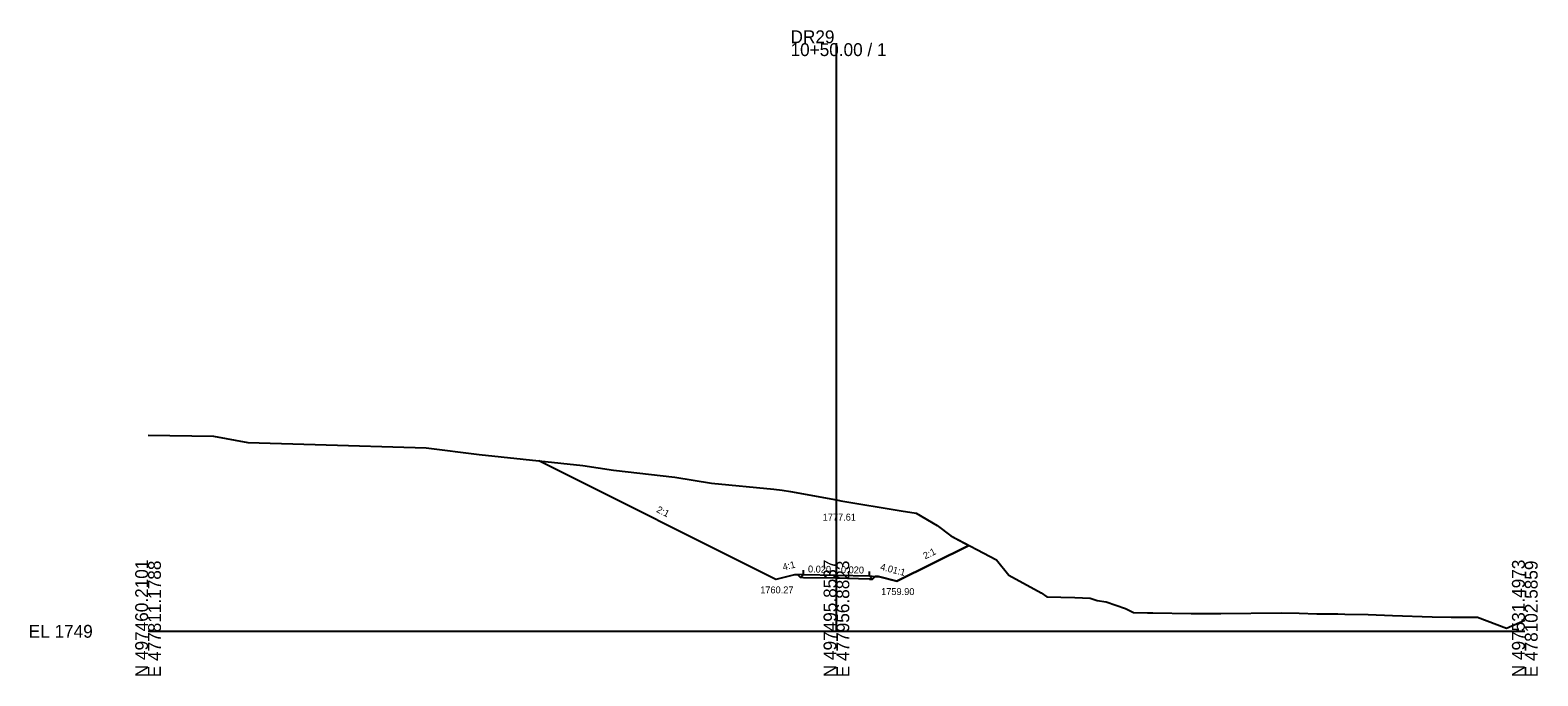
# Model space of a CAD drawing. Extents: x -26 to 303, y -10 to 4734.
# Drawn here: x -25.7 to 302.8, y 990.3 to 1130.9 of the extents above; entities that cross this region are included whole.
import ezdxf

# ---------------------------------------------------------------- set-up
doc = ezdxf.new("R2010")
doc.units = 0
for name, color, linetype in [('Exist Cross Section Cell', 7, 'Continuous'), ('Exist XS Center Line Elevation Label', 7, 'Continuous'), ('Exist XS Ground Line', 7, 'Continuous'), ('Prop XS Ditch Slope Text', 7, 'Continuous'), ('Prop XS Ditch Standard Text', 7, 'Continuous'), ('Prop XS Dump Level', 7, 'Continuous'), ('Prop XS Earthwork Shape', 7, 'Continuous'), ('Prop XS EOT Tick Mark', 7, 'Continuous'), ('Prop XS Finish Grade', 7, 'Continuous'), ('Prop XS Finish Grade Earthwork', 7, 'Continuous'), ('Prop XS Finish Grade Pavement', 7, 'Continuous'), ('Prop XS Pvmt Edge Slope', 7, 'Continuous'), ('Prop XS SE Text', 7, 'Continuous'), ('Prop XS Shoulder Borrow Shape', 7, 'Continuous'), ('Prop XS Side Slope Text', 7, 'Continuous'), ('Prop XS Subgrade Earthwork', 7, 'Continuous')]:
    doc.layers.add(name, color=color, linetype=linetype)

msp = doc.modelspace()

# ---------------------------------------------------------------- linework, layer by layer
at = {"layer": 'Exist Cross Section Cell'}
for p, q in [((150, 1000), (150, 1128.06)), ((0, 1000), (150, 1000)), ((150, 1000), (300, 1000))]:
    msp.add_line(p, q, dxfattribs=at)
at = {"layer": 'Exist XS Ground Line'}
msp.add_lwpolyline([(0, 1042.69), (14.27, 1042.47), (21.75, 1041.13), (36.4, 1040.66), (60.61, 1039.92), (72.14, 1038.47), (94.73, 1036.07), (101.42, 1035.12), (114.79, 1033.59), (122.81, 1032.28), (136.35, 1030.96), (138.15, 1030.74), (139.96, 1030.46), (150, 1028.61), (150.97, 1028.43), (164.13, 1026.23), (167.36, 1025.7), (171.98, 1023.04), (174.95, 1020.78), (184.9, 1015.53), (187.59, 1012.22), (194.64, 1008.37), (195.84, 1007.5), (201.96, 1007.34), (205.26, 1007.19), (206.79, 1006.69), (208.79, 1006.41), (213.01, 1004.95), (214.73, 1004.09), (217.76, 1004.01), (218.96, 1004), (227.3, 1003.9), (228.5, 1003.89), (233.79, 1003.86), (246.89, 1004.01), (250.83, 1003.95), (254.7, 1003.83), (255.27, 1003.83), (259.27, 1003.77), (260.75, 1003.76), (265.83, 1003.68), (271.17, 1003.47), (279.81, 1003.16), (283.97, 1003.1), (289.7, 1003.06), (293.89, 1001.5), (296.01, 1000.71), (300, 1002.41)], dxfattribs=at)
at = {"layer": 'Prop XS Dump Level'}
for p, q in [((142.83, 1012.35), (150, 1012.2)), ((150, 1012.2), (157.18, 1012.06))]:
    msp.add_line(p, q, dxfattribs=at)
at = {"layer": 'Prop XS Earthwork Shape'}
for points in [[(136.82, 1011.27), (85.14, 1037.09), (94.73, 1036.07), (101.42, 1035.12), (114.79, 1033.59), (122.81, 1032.28), (136.35, 1030.96), (138.15, 1030.74), (139.96, 1030.46), (150, 1028.61), (150.97, 1028.43), (164.13, 1026.23), (167.36, 1025.7), (171.98, 1023.04), (174.95, 1020.78), (178.86, 1018.72), (163.19, 1010.9), (159.19, 1011.9), (158.44, 1011.96), (157.86, 1011.38), (157.18, 1011.39), (150, 1011.54), (142.83, 1011.68), (142.17, 1011.69), (141.57, 1012.3), (140.83, 1012.27)], [(157.18, 1011.39), (150, 1011.54), (142.83, 1011.68), (142.17, 1011.69), (141.57, 1012.3), (140.83, 1012.27), (136.82, 1011.27), (85.14, 1037.09), (94.73, 1036.07), (101.42, 1035.12), (114.79, 1033.59), (122.81, 1032.28), (136.35, 1030.96), (138.15, 1030.74), (139.96, 1030.46), (150, 1028.61), (150.97, 1028.43), (164.13, 1026.23), (167.36, 1025.7), (171.98, 1023.04), (174.95, 1020.78), (178.86, 1018.72), (163.19, 1010.9), (159.19, 1011.9), (158.44, 1011.96), (157.86, 1011.38)]]:
    msp.add_lwpolyline(points, close=True, dxfattribs=at)
at = {"layer": 'Prop XS EOT Tick Mark'}
for p, q in [((142.83, 1012.35), (142.83, 1013.35)), ((157.18, 1012.06), (157.18, 1013.06))]:
    msp.add_line(p, q, dxfattribs=at)
at = {"layer": 'Prop XS Finish Grade'}
for p, q in [((142.83, 1012.35), (141.57, 1012.3)), ((157.18, 1012.06), (158.44, 1011.96))]:
    msp.add_line(p, q, dxfattribs=at)
at = {"layer": 'Prop XS Finish Grade Earthwork'}
for p, q in [((136.82, 1011.27), (85.14, 1037.09)), ((163.19, 1010.9), (178.86, 1018.72)), ((140.83, 1012.27), (136.82, 1011.27)), ((141.57, 1012.3), (140.83, 1012.27)), ((158.44, 1011.96), (159.19, 1011.9)), ((159.19, 1011.9), (163.19, 1010.9))]:
    msp.add_line(p, q, dxfattribs=at)
at = {"layer": 'Prop XS Finish Grade Pavement'}
for p, q in [((142.83, 1012.35), (150, 1012.2)), ((150, 1012.2), (157.18, 1012.06))]:
    msp.add_line(p, q, dxfattribs=at)
at = {"layer": 'Prop XS Pvmt Edge Slope'}
for p, q in [((142.83, 1012.35), (142.17, 1011.69)), ((157.18, 1012.06), (157.86, 1011.38))]:
    msp.add_line(p, q, dxfattribs=at)
at = {"layer": 'Prop XS Shoulder Borrow Shape'}
for points in [[(142.83, 1012.35), (141.57, 1012.3), (142.17, 1011.69)], [(157.18, 1012.06), (158.44, 1011.96), (157.86, 1011.38)]]:
    msp.add_lwpolyline(points, close=True, dxfattribs=at)
at = {"layer": 'Prop XS Subgrade Earthwork'}
for p, q in [((142.17, 1011.69), (141.57, 1012.3)), ((157.86, 1011.38), (158.44, 1011.96)), ((142.83, 1011.68), (142.17, 1011.69)), ((150, 1011.54), (142.83, 1011.68)), ((157.18, 1011.39), (150, 1011.54)), ((157.18, 1011.39), (157.86, 1011.38))]:
    msp.add_line(p, q, dxfattribs=at)

# ---------------------------------------------------------------- texts
at = {"layer": 'Exist Cross Section Cell'}
for s, p in [('DR29', (140, 1128.06)), ('10+50.00 / 1', (140, 1125.26)), ('EL 1749', (-26, 998.6))]:
    msp.add_text(s, height=2.8, dxfattribs=at).set_placement(p)
for s, p in [('N 497460.2101', (0, 990)), ('E 477811.1788', (2.8, 990)), ('N 497495.8537', (150, 990)), ('E 477956.8823', (152.8, 990)), ('N 497531.4973', (300, 990)), ('E 478102.5859', (302.8, 990))]:
    msp.add_text(s, height=2.8, rotation=90, dxfattribs=at).set_placement(p)
at = {"layer": 'Exist XS Center Line Elevation Label'}
msp.add_text('1777.61', height=1.5, dxfattribs=at).set_placement((147, 1024.11))
at = {"layer": 'Prop XS Ditch Slope Text'}
for s, rotation, p in [('4:1', 14.0283, (138.46, 1013.22)), ('4.01:1', 345.9841, (159.43, 1013.38))]:
    msp.add_text(s, height=1.5, rotation=rotation, dxfattribs=at).set_placement(p)
at = {"layer": 'Prop XS Ditch Standard Text'}
for s, p in [('1760.27', (133.39, 1008.27)), ('1759.90', (159.74, 1007.9))]:
    msp.add_text(s, height=1.5, dxfattribs=at).set_placement(p)
at = {"layer": 'Prop XS Dump Level'}
for p in [(140.83, 1012.23), (159.19, 1011.86)]:
    msp.add_text('Case1', height=0.04, dxfattribs=at).set_placement(p)
at = {"layer": 'Prop XS SE Text'}
for p in [(143.79, 1012.83), (150.97, 1012.68)]:
    msp.add_text('0.020', height=1.5, rotation=358.8542, dxfattribs=at).set_placement(p)
at = {"layer": 'Prop XS Side Slope Text'}
for rotation, p in [(333.4485, (110.64, 1026.03)), (26.5305, (169.34, 1015.64))]:
    msp.add_text('2:1', height=1.5, rotation=rotation, dxfattribs=at).set_placement(p)

doc.saveas('drawing.dxf')
